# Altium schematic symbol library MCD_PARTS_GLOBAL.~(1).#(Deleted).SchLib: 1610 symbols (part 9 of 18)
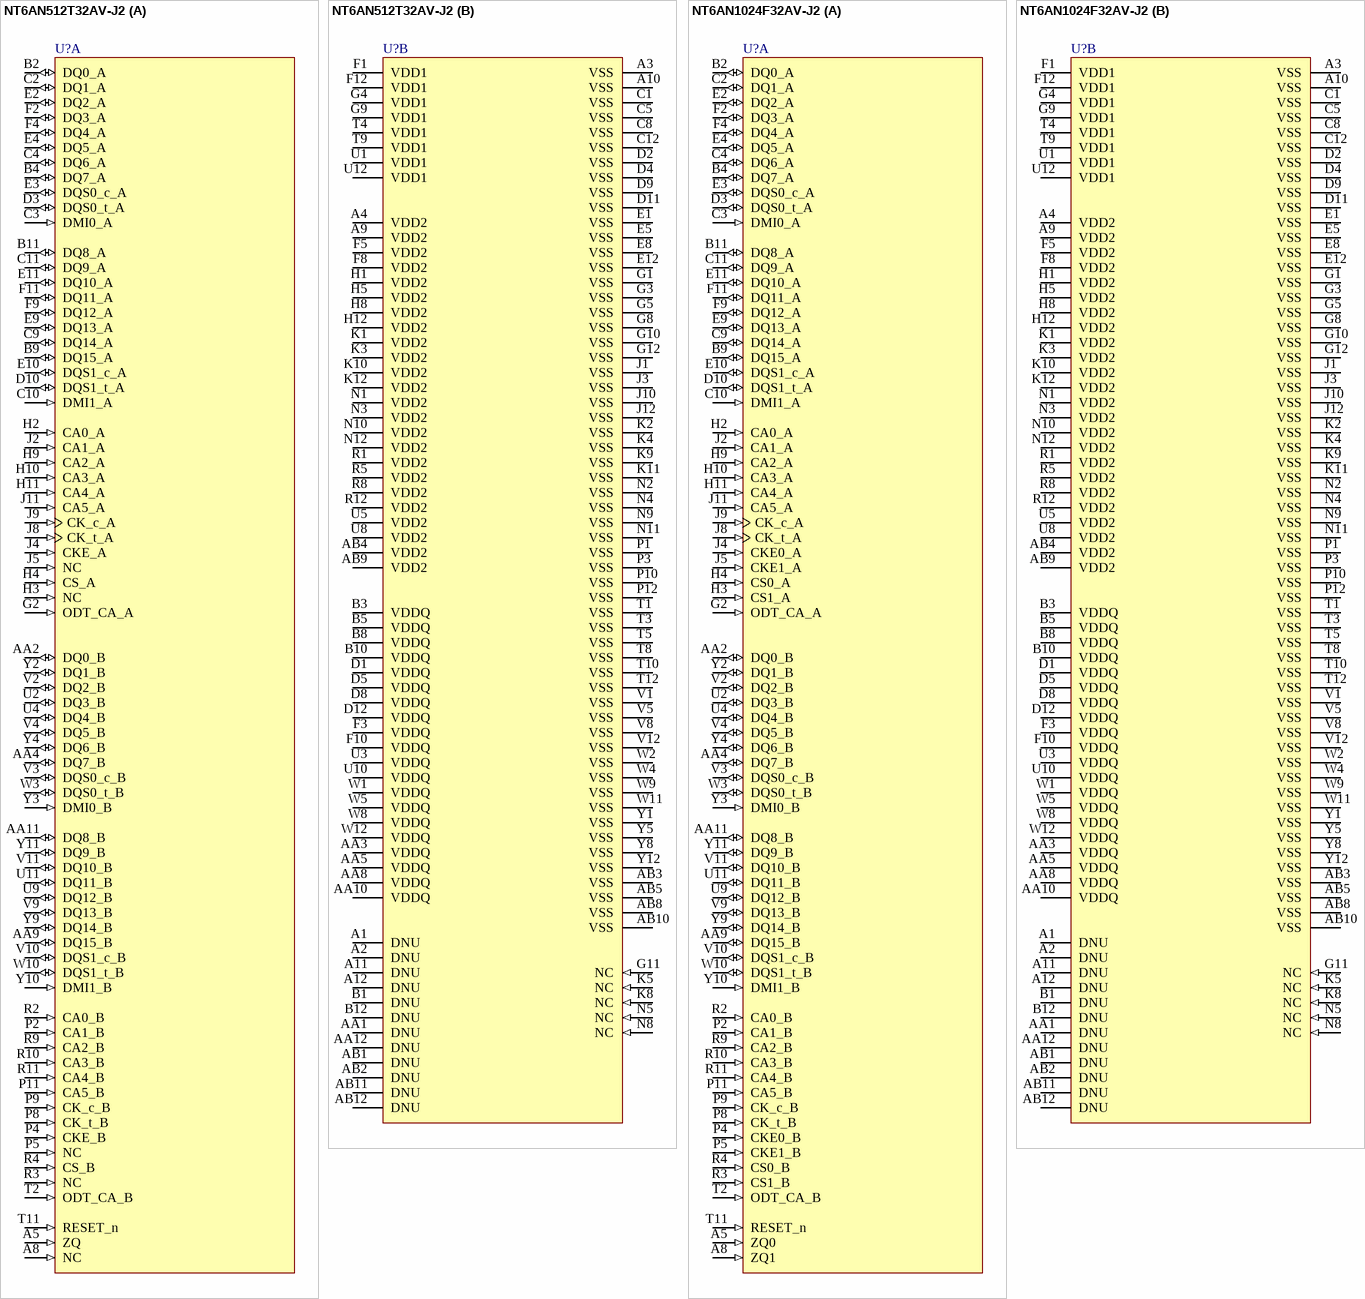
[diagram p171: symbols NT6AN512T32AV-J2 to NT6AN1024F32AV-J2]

## NT6AN1024F32AV-J2
designator U?
part A pins: A5 ZQ0 (in) "External impedance (240 ohm): This signal is used to calibrate the device output impedance.", A8 ZQ1 (in) "NC", AA2 DQ0_B (io) "Data input/output: Bidirectional data bus.", AA4 DQ7_B (io) "Data input/output: Bidirectional data bus.", AA9 DQ15_B (io) "Data input/output: Bidirectional data bus.", AA11 DQ8_B (io) "Data input/output: Bidirectional data bus.", B2 DQ0_A (io) "Data input/output: Bidirectional data bus.", B4 DQ7_A (io) "Data input/output: Bidirectional data bus.", B9 DQ15_A (io) "Data input/output: Bidirectional data bus.", B11 DQ8_A (io) "Data input/output: Bidirectional data bus.", C2 DQ1_A (io) "Data input/output: Bidirectional data bus.", C3 DMI0_A (in) "Input data mask: DM is an input mask signal for write data. Although DM ballsare input-only, the DM loading is designed to match that of DQ and DQS balls.DM[3:0] is DM for each of the four data bytes, respectively.", C4 DQ6_A (io) "Data input/output: Bidirectional data bus.", C9 DQ14_A (io) "Data input/output: Bidirectional data bus.", C10 DMI1_A (in) "Input data mask: DM is an input mask signal for write data. Although DM ballsare input-only, the DM loading is designed to match that of DQ and DQS balls.DM[3:0] is DM for each of the four data bytes, respectively.", C11 DQ9_A (io) "Data input/output: Bidirectional data bus.", D3 DQS0_t_A (io) "Data strobe: The data strobe is bidirectional (used for read and write data) andcomplementary (DQS and DQS#). It is edge-aligned output with read data andcentered input with write data. DQS[3:0]/DQS[3:0]# is DQS for each of (See Datasheet)", D10 DQS1_t_A (io) "Data strobe: The data strobe is bidirectional (used for read and write data) andcomplementary (DQS and DQS#). It is edge-aligned output with read data andcentered input with write data. DQS[3:0]/DQS[3:0]# is DQS for each of (See Datasheet)", E2 DQ2_A (io) "Data input/output: Bidirectional data bus.", E3 DQS0_c_A (io) "Data strobe: The data strobe is bidirectional (used for read and write data) andcomplementary (DQS and DQS#). It is edge-aligned output with read data andcentered input with write data. DQS[3:0]/DQS[3:0]# is DQS for each of (See Datasheet)", E4 DQ5_A (io) "Data input/output: Bidirectional data bus.", E9 DQ13_A (io) "Data input/output: Bidirectional data bus.", E10 DQS1_c_A (io) "Data strobe: The data strobe is bidirectional (used for read and write data) andcomplementary (DQS and DQS#). It is edge-aligned output with read data andcentered input with write data. DQS[3:0]/DQS[3:0]# is DQS for each of (See Datasheet)", E11 DQ10_A (io) "Data input/output: Bidirectional data bus.", F2 DQ3_A (io) "Data input/output: Bidirectional data bus.", F4 DQ4_A (io) "Data input/output: Bidirectional data bus.", F9 DQ12_A (io) "Data input/output: Bidirectional data bus.", F11 DQ11_A (io) "Data input/output: Bidirectional data bus.", G2 ODT_CA_A (in) "on die termination on CA", H2 CA0_A (in) "Command/address inputs: Provide the command and address inputs accordingto the command truth table.", H3 CS1_A (in) "NC", H4 CS0_A (in) "Chip select: CS# is considered part of the command code and is sampled at therising edge of CK.", H9 CA2_A (in) "Command/address inputs: Provide the command and address inputs accordingto the command truth table.", H10 CA3_A (in) "Command/address inputs: Provide the command and address inputs accordingto the command truth table.", H11 CA4_A (in) "Command/address inputs: Provide the command and address inputs accordingto the command truth table.", J2 CA1_A (in) "Command/address inputs: Provide the command and address inputs accordingto the command truth table.", J4 CKE0_A (in) "Clock enable: CKE HIGH activates and CKE LOW deactivates the internal clocksignals, input buffers, and output drivers. Power-saving modes are entered andexited via CKE transitions. CKE is considered part of the command code. (See Datasheet)", J5 CKE1_A (in) "NC", J8 CK_t_A (in) "Clock: CK and CK# are differential clock inputs. All CA inputs are sampled onboth rising and falling edges of CK. CS and CKE inputs are sampled at the risingedge of CK. AC timings are referenced to clock.", J9 CK_c_A (in) "Clock: CK and CK# are differential clock inputs. All CA inputs are sampled onboth rising and falling edges of CK. CS and CKE inputs are sampled at the risingedge of CK. AC timings are referenced to clock.", J11 CA5_A (in) "Command/address inputs: Provide the command and address inputs accordingto the command truth table.", P2 CA1_B (in) "Command/address inputs: Provide the command and address inputs accordingto the command truth table.", P4 CKE0_B (in) "Clock enable: CKE HIGH activates and CKE LOW deactivates the internal clocksignals, input buffers, and output drivers. Power-saving modes are entered andexited via CKE transitions. CKE is considered part of the command code. (See Datasheet)", P5 CKE1_B (in) "NC", P8 CK_t_B (in) "Clock: CK and CK# are differential clock inputs. All CA inputs are sampled onboth rising and falling edges of CK. CS and CKE inputs are sampled at the risingedge of CK. AC timings are referenced to clock.", P9 CK_c_B (in) "Clock: CK and CK# are differential clock inputs. All CA inputs are sampled onboth rising and falling edges of CK. CS and CKE inputs are sampled at the risingedge of CK. AC timings are referenced to clock.", P11 CA5_B (in) "Command/address inputs: Provide the command and address inputs accordingto the command truth table.", R2 CA0_B (in) "Command/address inputs: Provide the command and address inputs accordingto the command truth table.", R3 CS1_B (in) "NC", R4 CS0_B (in) "Chip select: CS# is considered part of the command code and is sampled at therising edge of CK.", R9 CA2_B (in) "Command/address inputs: Provide the command and address inputs accordingto the command truth table.", R10 CA3_B (in) "Command/address inputs: Provide the command and address inputs accordingto the command truth table.", R11 CA4_B (in) "Command/address inputs: Provide the command and address inputs accordingto the command truth table.", T2 ODT_CA_B (in) "on die termination on CA", T11 RESET_n (in) "Reset active low", U2 DQ3_B (io) "Data input/output: Bidirectional data bus.", U4 DQ4_B (io) "Data input/output: Bidirectional data bus.", U9 DQ12_B (io) "Data input/output: Bidirectional data bus.", U11 DQ11_B (io) "Data input/output: Bidirectional data bus.", V2 DQ2_B (io) "Data input/output: Bidirectional data bus.", V3 DQS0_c_B (io) "Data strobe: The data strobe is bidirectional (used for read and write data) andcomplementary (DQS and DQS#). It is edge-aligned output with read data andcentered input with write data. DQS[3:0]/DQS[3:0]# is DQS for each of (See Datasheet)", V4 DQ5_B (io) "Data input/output: Bidirectional data bus.", V9 DQ13_B (io) "Data input/output: Bidirectional data bus.", V10 DQS1_c_B (io) "Data strobe: The data strobe is bidirectional (used for read and write data) andcomplementary (DQS and DQS#). It is edge-aligned output with read data andcentered input with write data. DQS[3:0]/DQS[3:0]# is DQS for each of (See Datasheet)", V11 DQ10_B (io) "Data input/output: Bidirectional data bus.", W3 DQS0_t_B (io) "Data strobe: The data strobe is bidirectional (used for read and write data) andcomplementary (DQS and DQS#). It is edge-aligned output with read data andcentered input with write data. DQS[3:0]/DQS[3:0]# is DQS for each of (See Datasheet)", W10 DQS1_t_B (io) "Data strobe: The data strobe is bidirectional (used for read and write data) andcomplementary (DQS and DQS#). It is edge-aligned output with read data andcentered input with write data. DQS[3:0]/DQS[3:0]# is DQS for each of (See Datasheet)", Y2 DQ1_B (io) "Data input/output: Bidirectional data bus.", Y3 DMI0_B (in) "Input data mask: DM is an input mask signal for write data. Although DM ballsare input-only, the DM loading is designed to match that of DQ and DQS balls.DM[3:0] is DM for each of the four data bytes, respectively.", Y4 DQ6_B (io) "Data input/output: Bidirectional data bus.", Y9 DQ14_B (io) "Data input/output: Bidirectional data bus.", Y10 DMI1_B (in) "Input data mask: DM is an input mask signal for write data. Although DM ballsare input-only, the DM loading is designed to match that of DQ and DQS balls.DM[3:0] is DM for each of the four data bytes, respectively.", Y11 DQ9_B (io) "Data input/output: Bidirectional data bus."
part B pins: A1 DNU "Do not use: Must be grounded or left floating.", A2 DNU "Do not use: Must be grounded or left floating.", A3 VSS (power) "Common ground.", A4 VDD2 (power) "Core power: Supply 2.", A9 VDD2 (power) "Core power: Supply 2.", A10 VSS (power) "Common ground.", A11 DNU "Do not use: Must be grounded or left floating.", A12 DNU "Do not use: Must be grounded or left floating.", AA1 DNU "Do not use: Must be grounded or left floating.", AA3 VDDQ (power) "DQ power supply: Isolated on the die for improved noise immunity.", AA5 VDDQ (power) "DQ power supply: Isolated on the die for improved noise immunity.", AA8 VDDQ (power) "DQ power supply: Isolated on the die for improved noise immunity.", AA10 VDDQ (power) "DQ power supply: Isolated on the die for improved noise immunity.", AA12 DNU "Do not use: Must be grounded or left floating.", AB1 DNU "Do not use: Must be grounded or left floating.", AB2 DNU "Do not use: Must be grounded or left floating.", AB3 VSS "Common ground.", AB4 VDD2 (power) "Core power: Supply 2.", AB5 VSS "Common ground.", AB8 VSS "Common ground.", AB9 VDD2 (power) "Core power: Supply 2.", AB10 VSS "Common ground.", AB11 DNU "Do not use: Must be grounded or left floating.", AB12 DNU "Do not use: Must be grounded or left floating.", B1 DNU "Do not use: Must be grounded or left floating.", B3 VDDQ (power) "DQ power supply: Isolated on the die for improved noise immunity.", B5 VDDQ (power) "DQ power supply: Isolated on the die for improved noise immunity.", B8 VDDQ (power) "DQ power supply: Isolated on the die for improved noise immunity.", B10 VDDQ (power) "DQ power supply: Isolated on the die for improved noise immunity.", B12 DNU "Do not use: Must be grounded or left floating.", C1 VSS (power) "Common ground.", C5 VSS (power) "Common ground.", C8 VSS (power) "Common ground.", C12 VSS (power) "Common ground.", D1 VDDQ (power) "DQ power supply: Isolated on the die for improved noise immunity.", D2 VSS (power) "Common ground.", D4 VSS (power) "Common ground.", D5 VDDQ (power) "DQ power supply: Isolated on the die for improved noise immunity.", D8 VDDQ (power) "DQ power supply: Isolated on the die for improved noise immunity.", D9 VSS (power) "Common ground.", D11 VSS (power) "Common ground.", D12 VDDQ (power) "DQ power supply: Isolated on the die for improved noise immunity.", E1 VSS (power) "Common ground.", E5 VSS (power) "Common ground.", E8 VSS (power) "Common ground.", E12 VSS (power) "Common ground.", F1 VDD1 (power) "Core power: Supply 1.", F3 VDDQ (power) "DQ power supply: Isolated on the die for improved noise immunity.", F5 VDD2 (power) "Core power: Supply 2.", F8 VDD2 (power) "Core power: Supply 2.", F10 VDDQ (power) "DQ power supply: Isolated on the die for improved noise immunity.", F12 VDD1 (power) "Core power: Supply 1.", G1 VSS (power) "Common ground.", G3 VSS (power) "Common ground.", G4 VDD1 (power) "Core power: Supply 1.", G5 VSS (power) "Common ground.", G8 VSS (power) "Common ground.", G9 VDD1 (power) "Core power: Supply 1.", G10 VSS (power) "Common ground.", G11 NC (in) "Not connected", G12 VSS (power) "Common ground.", H1 VDD2 (power) "Core power: Supply 2.", H5 VDD2 (power) "Core power: Supply 2.", H8 VDD2 (power) "Core power: Supply 2.", H12 VDD2 (power) "Core power: Supply 2.", J1 VSS (power) "Common ground.", J3 VSS (power) "Common ground.", J10 VSS (power) "Common ground.", J12 VSS (power) "Common ground.", K1 VDD2 (power) "Core power: Supply 2.", K2 VSS (power) "Common ground.", K3 VDD2 (power) "Core power: Supply 2.", K4 VSS (power) "Common ground.", K5 NC (in) "Not connected", K8 NC (in) "Not connected", K9 VSS (power) "Common ground.", K10 VDD2 (power) "Core power: Supply 2.", K11 VSS "Common ground.", K12 VDD2 (power) "Core power: Supply 2.", N1 VDD2 (power) "Core power: Supply 2.", N2 VSS "Common ground.", N3 VDD2 (power) "Core power: Supply 2.", N4 VSS "Common ground.", N5 NC (in) "Not connected", N8 NC (in) "Not connected", N9 VSS "Common ground.", N10 VDD2 (power) "Core power: Supply 2.", N11 VSS "Common ground.", N12 VDD2 (power) "Core power: Supply 2.", P1 VSS "Common ground.", P3 VSS (power) "Common ground.", P10 VSS (power) "Common ground.", P12 VSS "Common ground.", R1 VDD2 (power) "Core power: Supply 2.", R5 VDD2 (power) "Core power: Supply 2.", R8 VDD2 (power) "Core power: Supply 2.", R12 VDD2 (power) "Core power: Supply 2.", T1 VSS "Common ground.", T3 VSS "Common ground.", T4 VDD1 (power) "Core power: Supply 1.", T5 VSS "Common ground.", T8 VSS "Common ground.", T9 VDD1 (power) "Core power: Supply 1.", T10 VSS "Common ground.", T12 VSS "Common ground.", U1 VDD1 (power) "Core power: Supply 1.", U3 VDDQ (power) "DQ power supply: Isolated on the die for improved noise immunity.", U5 VDD2 (power) "Core power: Supply 2.", U8 VDD2 (power) "Core power: Supply 2.", U10 VDDQ (power) "DQ power supply: Isolated on the die for improved noise immunity.", U12 VDD1 (power) "Core power: Supply 1.", V1 VSS (power) "Common ground.", V5 VSS (power) "Common ground.", V8 VSS "Common ground.", V12 VSS "Common ground.", W1 VDDQ (power) "DQ power supply: Isolated on the die for improved noise immunity.", W2 VSS "Common ground.", W4 VSS "Common ground.", W5 VDDQ (power) "DQ power supply: Isolated on the die for improved noise immunity.", W8 VDDQ (power) "DQ power supply: Isolated on the die for improved noise immunity.", W9 VSS "Common ground.", W11 VSS "Common ground.", W12 VDDQ (power) "DQ power supply: Isolated on the die for improved noise immunity.", Y1 VSS "Common ground.", Y5 VSS "Common ground.", Y8 VSS "Common ground.", Y12 VSS "Common ground."

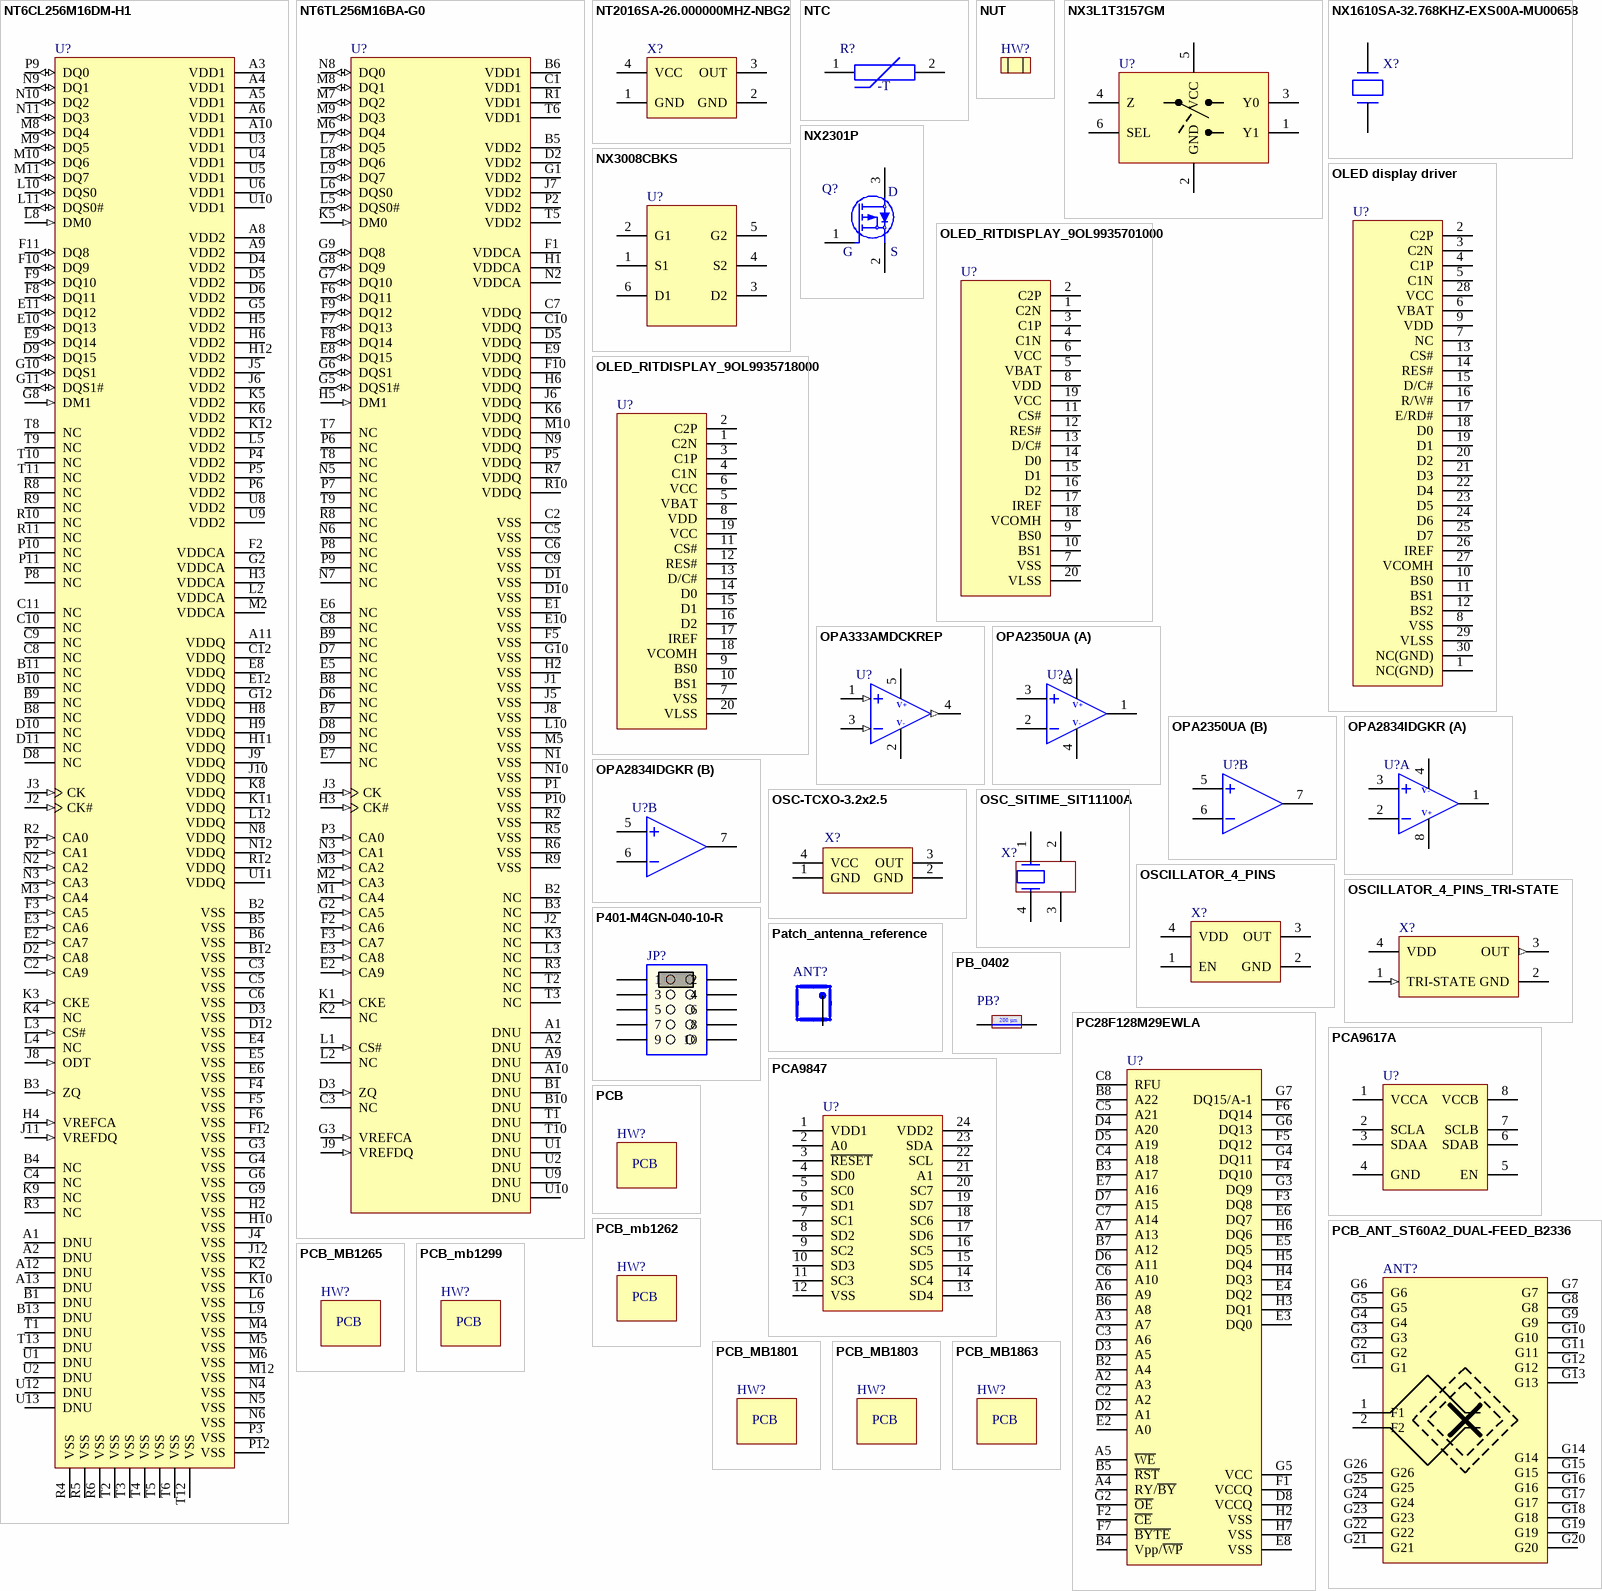
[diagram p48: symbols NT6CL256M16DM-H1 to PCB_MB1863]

## NT6CL256M16DM-H1
designator U?
pins: A1 DNU "Do not use: Must be grounded or left floating.", A2 DNU "Do not use: Must be grounded or left floating.", A3 VDD1 (power) "Core power: Supply 1.", A4 VDD1 (power) "Core power: Supply 1.", A5 VDD1 (power) "Core power: Supply 1.", A6 VDD1 (power) "Core power: Supply 1.", A8 VDD2 (power) "Core power: Supply 2.", A9 VDD2 (power) "Core power: Supply 2.", A10 VDD1 (power) "Core power: Supply 1.", A11 VDDQ (power) "DQ power supply: Isolated on the die for improved noise immunity.", A12 DNU "Do not use: Must be grounded or left floating.", A13 DNU "Do not use: Must be grounded or left floating.", B1 DNU "Do not use: Must be grounded or left floating.", B2 VSS (power) "Common ground", B3 ZQ (in) "External impedance (240 ohm): This signal is used to calibrate the device output impedance.", B4 NC "No connect: Not internally connected.", B5 VSS (power) "Common ground", B6 VSS (power) "Common ground", B8 NC "No connect: Not internally connected.", B9 NC "No connect: Not internally connected.", B10 NC "No connect: Not internally connected.", B11 NC "No connect: Not internally connected.", B12 VSS (power) "Common ground", B13 DNU "Do not use: Must be grounded or left floating.", C2 CA9 (in) "Command/address inputs: Provide the command and address inputs accordingto the command truth table.", C3 VSS (power) "Common ground", C4 NC "No connect: Not internally connected.", C5 VSS (power) "Common ground", C6 VSS (power) "Common ground", C8 NC "No connect: Not internally connected.", C9 NC "No connect: Not internally connected.", C10 NC "No connect: Not internally connected.", C11 NC "No connect: Not internally connected.", C12 VDDQ (power) "DQ power supply: Isolated on the die for improved noise immunity.", D2 CA8 (in) "Command/address inputs: Provide the command and address inputs accordingto the command truth table.", D3 VSS (power) "Common ground", D4 VDD2 (power) "Core power: Supply 2.", D5 VDD2 (power) "Core power: Supply 2.", D6 VDD2 (power) "Core power: Supply 2.", D8 NC "No connect: Not internally connected.", D9 DQ15 (io) "Data input/output: Bidirectional data bus.", D10 NC "No connect: Not internally connected.", D11 NC "No connect: Not internally connected.", D12 VSS (power) "Common ground", E2 CA7 (in) "Command/address inputs: Provide the command and address inputs accordingto the command truth table.", E3 CA6 (in) "Command/address inputs: Provide the command and address inputs accordingto the command truth table.", E4 VSS (power) "Common ground", E5 VSS (power) "Common ground", E6 VSS (power) "Common ground", E8 VDDQ (power) "DQ power supply: Isolated on the die for improved noise immunity.", E9 DQ14 (io) "Data input/output: Bidirectional data bus.", E10 DQ13 (io) "Data input/output: Bidirectional data bus.", E11 DQ12 (io) "Data input/output: Bidirectional data bus.", E12 VDDQ (power) "DQ power supply: Isolated on the die for improved noise immunity.", F2 VDDCA (power) "Command/address power supply: Command/address power supply.", F3 CA5 (in) "Command/address inputs: Provide the command and address inputs accordingto the command truth table.", F4 VSS (power) "Common ground", F5 VSS (power) "Common ground", F6 VSS (power) "Common ground", F8 DQ11 (io) "Data input/output: Bidirectional data bus.", F9 DQ10 (io) "Data input/output: Bidirectional data bus.", F10 DQ9 (io) "Data input/output: Bidirectional data bus.", F11 DQ8 (io) "Data input/output: Bidirectional data bus.", F12 VSS (power) "Common ground", G2 VDDCA (power) "Command/address power supply: Command/address power supply.", G3 VSS (power) "Common ground", G4 VSS (power) "Common ground", G5 VDD2 (power) "Core power: Supply 2.", G6 VSS (power) "Common ground", G8 DM1 (in) "Input data mask: DM is an input mask signal for write data. Although DM ballsare input-only, the DM loading is designed to match that of DQ and DQS balls.DM[3:0] is DM for each of the four data bytes, respectively.", G9 VSS (power) "Common ground", G10 DQS1 (io) "Data strobe: The data strobe is bidirectional (used for read and write data) andcomplementary (DQS and DQS#). It is edge-aligned output with read data andcentered input with write data. DQS[3:0]/DQS[3:0]# is DQS for each of (See Datasheet)", G11 DQS1# (io) "Data strobe: The data strobe is bidirectional (used for read and write data) andcomplementary (DQS and DQS#). It is edge-aligned output with read data andcentered input with write data. DQS[3:0]/DQS[3:0]# is DQS for each of (See Datasheet)", G12 VDDQ (power) "DQ power supply: Isolated on the die for improved noise immunity.", H2 VSS (power) "Common ground", H3 VDDCA (power) "Command/address power supply: Command/address power supply.", H4 VREFCA (in) "Reference voltage: VREFCA is reference for command/address input buffers,VREFDQ is reference for DQ input buffers.", H5 VDD2 (power) "Core power: Supply 2.", H6 VDD2 (power) "Core power: Supply 2.", H8 VDDQ (power) "DQ power supply: Isolated on the die for improved noise immunity.", H9 VDDQ (power) "DQ power supply: Isolated on the die for improved noise immunity.", H10 VSS (power) "Common ground", H11 VDDQ (power) "DQ power supply: Isolated on the die for improved noise immunity.", H12 VDD2 (power) "Core power: Supply 2.", J2 CK# (in) "Clock: CK and CK# are differential clock inputs. All CA inputs are sampled onboth rising and falling edges of CK. CS and CKE inputs are sampled at the risingedge of CK. AC timings are referenced to clock.", J3 CK (in) "Clock: CK and CK# are differential clock inputs. All CA inputs are sampled onboth rising and falling edges of CK. CS and CKE inputs are sampled at the risingedge of CK. AC timings are referenced to clock.", J4 VSS (power) "Common ground", J5 VDD2 (power) "Core power: Supply 2.", J6 VDD2 (power) "Core power: Supply 2.", J8 ODT (in) "On Die Termination. If ODT function is not used, pin is NC.", J9 VDDQ (power) "DQ power supply: Isolated on the die for improved noise immunity.", J10 VDDQ (power) "DQ power supply: Isolated on the die for improved noise immunity.", J11 VREFDQ (in) "Reference voltage: VREFCA is reference for command/address input buffers,VREFDQ is reference for DQ input buffers.", J12 VSS (power) "Common ground", K2 VSS (power) "Common ground", K3 CKE (in) "Clock enable: CKE HIGH activates and CKE LOW deactivates the internal clocksignals, input buffers, and output drivers. Power-saving modes are entered andexited via CKE transitions. CKE is considered part of the command code. (See Datasheet)", K4 NC "No connect: Not internally connected.", K5 VDD2 (power) "Core power: Supply 2.", K6 VDD2 (power) "Core power: Supply 2.", K8 VDDQ (power) "DQ power supply: Isolated on the die for improved noise immunity.", K9 NC "No connect: Not internally connected.", K10 VSS (power) "Common ground", K11 VDDQ (power) "DQ power supply: Isolated on the die for improved noise immunity.", K12 VDD2 (power) "Core power: Supply 2.", L2 VDDCA (power) "Command/address power supply: Command/address power supply.", L3 CS# (in) "Chip select: CS# is considered part of the command code and is sampled at therising edge of CK.", L4 NC "No connect: Not internally connected.", L5 VDD2 (power) "Core power: Supply 2.", L6 VSS (power) "Common ground", L8 DM0 (in) "Input data mask: DM is an input mask signal for write data. Although DM ballsare input-only, the DM loading is designed to match that of DQ and DQS balls.DM[3:0] is DM for each of the four data bytes, respectively.", L9 VSS (power) "Common ground", L10 DQS0 (io) "Data strobe: The data strobe is bidirectional (used for read and write data) andcomplementary (DQS and DQS#). It is edge-aligned output with read data andcentered input with write data. DQS[3:0]/DQS[3:0]# is DQS for each of (See Datasheet)", L11 DQS0# (io) "Data strobe: The data strobe is bidirectional (used for read and write data) andcomplementary (DQS and DQS#). It is edge-aligned output with read data andcentered input with write data. DQS[3:0]/DQS[3:0]# is DQS for each of (See Datasheet)", L12 VDDQ (power) "DQ power supply: Isolated on the die for improved noise immunity.", M2 VDDCA (power) "Command/address power supply: Command/address power supply.", M3 CA4 (in) "Command/address inputs: Provide the command and address inputs accordingto the command truth table.", M4 VSS (power) "Common ground", M5 VSS (power) "Common ground", M6 VSS (power) "Common ground", M8 DQ4 (io) "Data input/output: Bidirectional data bus.", M9 DQ5 (io) "Data input/output: Bidirectional data bus.", M10 DQ6 (io) "Data input/output: Bidirectional data bus.", M11 DQ7 (io) "Data input/output: Bidirectional data bus.", M12 VSS (power) "Common ground", N2 CA2 (in) "Command/address inputs: Provide the command and address inputs accordingto the command truth table.", N3 CA3 (in) "Command/address inputs: Provide the command and address inputs accordingto the command truth table.", N4 VSS (power) "Common ground", N5 VSS (power) "Common ground", N6 VSS (power) "Common ground", N8 VDDQ (power) "DQ power supply: Isolated on the die for improved noise immunity.", N9 DQ1 (io) "Data input/output: Bidirectional data bus.", N10 DQ2 (io) "Data input/output: Bidirectional data bus.", N11 DQ3 (io) "Data input/output: Bidirectional data bus.", N12 VDDQ (power) "DQ power supply: Isolated on the die for improved noise immunity.", P2 CA1 (in) "Command/address inputs: Provide the command and address inputs accordingto the command truth table.", P3 VSS (power) "Common ground", P4 VDD2 (power) "Core power: Supply 2.", P5 VDD2 (power) "Core power: Supply 2.", P6 VDD2 (power) "Core power: Supply 2.", P8 NC "No connect: Not internally connected.", P9 DQ0 (io) "Data input/output: Bidirectional data bus.", P10 NC "No connect: Not internally connected.", P11 NC "No connect: Not internally connected.", P12 VSS (power) "Common ground", R2 CA0 (in) "Command/address inputs: Provide the command and address inputs accordingto the command truth table.", R3 NC "No connect: Not internally connected.", R4 VSS (power) "Common ground", R5 VSS (power) "Common ground", R6 VSS (power) "Common ground", R8 NC "No connect: Not internally connected.", R9 NC "No connect: Not internally connected.", R10 NC "No connect: Not internally connected.", R11 NC "No connect: Not internally connected.", R12 VDDQ (power) "DQ power supply: Isolated on the die for improved noise immunity.", T1 DNU "Do not use: Must be grounded or left floating.", T2 VSS (power) "Common ground", T3 VSS (power) "Common ground", T4 VSS (power) "Common ground", T5 VSS (power) "Common ground", T6 VSS (power) "Common ground", T8 NC "No connect: Not internally connected.", T9 NC "No connect: Not internally connected.", T10 NC "No connect: Not internally connected.", T11 NC "No connect: Not internally connected.", T12 VSS (power) "Common ground", T13 DNU "Do not use: Must be grounded or left floating.", U1 DNU "Do not use: Must be grounded or left floating.", U2 DNU "Do not use: Must be grounded or left floating.", U3 VDD1 (power) "Core power: Supply 1.", U4 VDD1 (power) "Core power: Supply 1.", U5 VDD1 (power) "Core power: Supply 1.", U6 VDD1 (power) "Core power: Supply 1.", U8 VDD2 (power) "Core power: Supply 2.", U9 VDD2 (power) "Core power: Supply 2.", U10 VDD1 (power) "Core power: Supply 1.", U11 VDDQ (power) "DQ power supply: Isolated on the die for improved noise immunity.", U12 DNU "Do not use: Must be grounded or left floating.", U13 DNU "Do not use: Must be grounded or left floating."

## NT6TL256M16BA-G0
designator U?
pins: A1 DNU "Do not use: Must be grounded or left floating.", A2 DNU "Do not use: Must be grounded or left floating.", A9 DNU "Do not use: Must be grounded or left floating.", A10 DNU "Do not use: Must be grounded or left floating.", B1 DNU "Do not use: Must be grounded or left floating.", B2 NC "No connect: Not internally connected.", B3 NC "No connect: Not internally connected.", B5 VDD2 (power) "Core power: Supply 2.", B6 VDD1 (power) "Core power: Supply 1.", B7 NC "No connect: Not internally connected.", B8 NC "No connect: Not internally connected.", B9 NC "No connect: Not internally connected.", B10 DNU "Do not use: Must be grounded or left floating.", C1 VDD1 (power) "Core power: Supply 1.", C2 VSS (power) "Common ground.", C3 NC "No connect: Not internally connected.", C5 VSS (power) "Common ground.", C6 VSS (power) "Common ground.", C7 VDDQ (power) "DQ power supply: Isolated on the die for improved noise immunity.", C8 NC "No connect: Not internally connected.", C9 VSS (power) "Common ground.", C10 VDDQ (power) "DQ power supply: Isolated on the die for improved noise immunity.", D1 VSS (power) "Common ground", D2 VDD2 (power) "Core power: Supply 2.", D3 ZQ (in) "External impedance (240 ohm): This signal is used to calibrate the device output impedance.", D5 VDDQ (power) "DQ power supply: Isolated on the die for improved noise immunity.", D6 NC "No connect: Not internally connected.", D7 NC "No connect: Not internally connected.", D8 NC "No connect: Not internally connected.", D9 NC "No connect: Not internally connected.", D10 VSS (power) "Common ground.", E1 VSS (power) "Common ground.", E2 CA9 (in) "Command/address inputs: Provide the command and address inputs accordingto the command truth table.", E3 CA8 (in) "Command/address inputs: Provide the command and address inputs accordingto the command truth table.", E5 NC "No connect: Not internally connected.", E6 NC "No connect: Not internally connected.", E7 NC "No connect: Not internally connected.", E8 DQ15 (io) "Data input/output: Bidirectional data bus.", E9 VDDQ (power) "DQ power supply: Isolated on the die for improved noise immunity.", E10 VSS (power) "Common ground.", F1 VDDCA (power) "Command/address power supply: Command/address power supply.", F2 CA6 (in) "Command/address inputs: Provide the command and address inputs accordingto the command truth table.", F3 CA7 (in) "Command/address inputs: Provide the command and address inputs accordingto the command truth table.", F5 VSS (power) "Common ground.", F6 DQ11 (io) "Data input/output: Bidirectional data bus.", F7 DQ13 (io) "Data input/output: Bidirectional data bus.", F8 DQ14 (io) "Data input/output: Bidirectional data bus.", F9 DQ12 (io) "Data input/output: Bidirectional data bus.", F10 VDDQ (power) "DQ power supply: Isolated on the die for improved noise immunity.", G1 VDD2 (power) "Core power: Supply 2.", G2 CA5 (in) "Command/address inputs: Provide the command and address inputs accordingto the command truth table.", G3 VREFCA (in) "Reference voltage: VREFCA is reference for command/address input buffers,VREFDQ is reference for DQ input buffers.", G5 DQS1# (io) "Data strobe: The data strobe is bidirectional (used for read and write data) andcomplementary (DQS and DQS#). It is edge-aligned output with read data andcentered input with write data. DQS[1:0]/DQS[1:0]# is DQS for each of (See Datasheet)", G6 DQS1 (io) "Data strobe: The data strobe is bidirectional (used for read and write data) andcomplementary (DQS and DQS#). It is edge-aligned output with read data andcentered input with write data. DQS[1:0]/DQS[1:0]# is DQS for each of (See Datasheet)", G7 DQ10 (io) "Data input/output: Bidirectional data bus.", G8 DQ9 (io) "Data input/output: Bidirectional data bus.", G9 DQ8 (io) "Data input/output: Bidirectional data bus.", G10 VSS (power) "Common ground.", H1 VDDCA (power) "Command/address power supply: Command/address power supply.", H2 VSS (power) "Common ground", H3 CK# (in) "Clock: CK and CK# are differential clock inputs. All CA inputs are sampled onboth rising and falling edges of CK. CS and CKE inputs are sampled at the risingedge of CK. AC timings are referenced to clock.", H5 DM1 (in) "Input data mask: DM is an input mask signal for write data. Although DM ballsare input-only, the DM loading is designed to match that of DQ and DQS balls.DM[3:0] is DM for each of the four data bytes, respectively.", H6 VDDQ (power) "DQ power supply: Isolated on the die for improved noise immunity.", J1 VSS (power) "Common ground.", J2 NC "No connect: Not internally connected.", J3 CK (in) "Clock: CK and CK# are differential clock inputs. All CA inputs are sampled onboth rising and falling edges of CK. CS and CKE inputs are sampled at the risingedge of CK. AC timings are referenced to clock.", J5 VSS (power) "Common ground.", J6 VDDQ (power) "DQ power supply: Isolated on the die for improved noise immunity.", J7 VDD2 (power) "Core power: Supply 2.", J8 VSS (power) "Common ground", J9 VREFDQ (in) "Reference voltage: VREFCA is reference for command/address input buffers,VREFDQ is reference for DQ input buffers.", K1 CKE (in) "Clock enable: CKE HIGH activates and CKE LOW deactivates the internal clocksignals, input buffers, and output drivers. Power-saving modes are entered andexited via CKE transitions. CKE is considered part of the command code. (See Datasheet)", K2 NC "No connect: Not internally connected.", K3 NC "No connect: Not internally connected.", K5 DM0 (in) "Input data mask: DM is an input mask signal for write data. Although DM ballsare input-only, the DM loading is designed to match that of DQ and DQS balls.DM[3:0] is DM for each of the four data bytes, respectively.", K6 VDDQ (power) "DQ power supply: Isolated on the die for improved noise immunity.", L1 CS# (in) "Chip select: CS# is considered part of the command code and is sampled at therising edge of CK.", L2 NC "No connect: Not internally connected.", L3 NC "No connect: Not internally connected.", L5 DQS0# (io) "Data strobe: The data strobe is bidirectional (used for read and write data) andcomplementary (DQS and DQS#). It is edge-aligned output with read data andcentered input with write data. DQS[1:0]/DQS[1:0]# is DQS for each of (See Datasheet)", L6 DQS0 (io) "Data strobe: The data strobe is bidirectional (used for read and write data) andcomplementary (DQS and DQS#). It is edge-aligned output with read data andcentered input with write data. DQS[1:0]/DQS[1:0]# is DQS for each of (See Datasheet)", L7 DQ5 (io) "Data input/output: Bidirectional data bus.", L8 DQ6 (io) "Data input/output: Bidirectional data bus.", L9 DQ7 (io) "Data input/output: Bidirectional data bus.", L10 VSS (power) "Common ground.", M1 CA4 (in) "Command/address inputs: Provide the command and address inputs accordingto the command truth table.", M2 CA3 (in) "Command/address inputs: Provide the command and address inputs accordingto the command truth table.", M3 CA2 (in) "Command/address inputs: Provide the command and address inputs accordingto the command truth table.", M5 VSS (power) "Common ground.", M6 DQ4 (io) "Data input/output: Bidirectional data bus.", M7 DQ2 (io) "Data input/output: Bidirectional data bus.", M8 DQ1 (io) "Data input/output: Bidirectional data bus.", M9 DQ3 (io) "Data input/output: Bidirectional data bus.", M10 VDDQ (power) "DQ power supply: Isolated on the die for improved noise immunity.", N1 VSS (power) "Common ground.", N2 VDDCA (power) "Command/address power supply: Command/address power supply.", N3 CA1 (in) "Command/address inputs: Provide the command and address inputs accordingto the command truth table.", N5 NC "No connect: Not internally connected.", N6 NC "No connect: Not internally connected.", N7 NC "No connect: Not internally connected.", N8 DQ0 (io) "Data input/output: Bidirectional data bus.", N9 VDDQ (power) "DQ power supply: Isolated on the die for improved noise immunity.", N10 VSS (power) "Common ground.", P1 VSS (power) "Common ground", P2 VDD2 (power) "Core power: Supply 2.", P3 CA0 (in) "Command/address inputs: Provide the command and address inputs accordingto the command truth table.", P5 VDDQ (power) "DQ power supply: Isolated on the die for improved noise immunity.", P6 NC "No connect: Not internally connected.", P7 NC "No connect: Not internally connected.", P8 NC "No connect: Not internally connected.", P9 NC "No connect: Not internally connected.", P10 VSS (power) "Common ground.", R1 VDD1 (power) "Core power: Supply 1.", R2 VSS (power) "Common ground", R3 NC "No connect: Not internally connected.", R5 VSS (power) "Common ground", R6 VSS (power) "Common ground.", R7 VDDQ (power) "DQ power supply: Isolated on the die for improved noise immunity.", R8 NC "No connect: Not internally connected.", R9 VSS (power) "Common ground.", R10 VDDQ (power) "DQ power supply: Isolated on the die for improved noise immunity.", T1 DNU "Do not use: Must be grounded or left floating.", T2 NC "No connect: Not internally connected.", T3 NC "No connect: Not internally connected.", T5 VDD2 (power) "Core power: Supply 2.", T6 VDD1 (power) "Core power: Supply 1.", T7 NC "No connect: Not internally connected.", T8 NC "No connect: Not internally connected.", T9 NC "No connect: Not internally connected.", T10 DNU "Do not use: Must be grounded or left floating.", U1 DNU "Do not use: Must be grounded or left floating.", U2 DNU "Do not use: Must be grounded or left floating.", U9 DNU "Do not use: Must be grounded or left floating.", U10 DNU "Do not use: Must be grounded or left floating."

## NT2016SA-26.000000MHZ-NBG2
designator X?
pins: 1 GND, 2 GND, 3 OUT, 4 VCC

## NTC
designator R?
pins: 1, 2

## NUT
designator HW?  (mechanical)

## NX3L1T3157GM
designator U?
pins: 1 Y1, 2 GND, 3 Y0, 4 Z, 5 VCC, 6 SEL

## NX1610SA-32.768KHZ-EXS00A-MU00658
designator X?
pins: 1 X1, 2 X2

## NX2301P
designator Q?
pins: 1 G, 2 S, 3 D

## NX3008CBKS
designator U?
pins: 1 S1, 2 G1, 3 D2, 4 S2, 5 G2, 6 D1

## OLED display driver
designator U?
pins: 1 NC(GND), 2 C2P, 3 C2N, 4 C1P, 5 C1N, 6 VBAT, 7 NC, 8 VSS, 9 VDD, 10 BS0, 11 BS1, 12 BS2, 13 CS#, 14 RES#, 15 D/C#, 16 R/W#, 17 E/RD#, 18 D0, 19 D1, 20 D2, 21 D3, 22 D4, 23 D5, 24 D6, 25 D7, 26 IREF, 27 VCOMH, 28 VCC, 29 VLSS, 30 NC(GND)

## OLED_RITDISPLAY_9OL9935701000
designator U?
pins: 1 C2N, 2 C2P, 3 C1P, 4 C1N, 5 VBAT, 6 VCC, 7 VSS, 8 VDD, 9 BS0, 10 BS1, 11 CS#, 12 RES#, 13 D/C#, 14 D0, 15 D1, 16 D2, 17 IREF, 18 VCOMH, 19 VCC, 20 VLSS

## OLED_RITDISPLAY_9OL9935718000
designator U?
pins: 1 C2N, 2 C2P, 3 C1P, 4 C1N, 5 VBAT, 6 VCC, 7 VSS, 8 VDD, 9 BS0, 10 BS1, 11 CS#, 12 RES#, 13 D/C#, 14 D0, 15 D1, 16 D2, 17 IREF, 18 VCOMH, 19 VCC, 20 VLSS

## OPA333AMDCKREP
designator U?
pins: 1 (in), 2 (power), 3 (in), 4 (out), 5 (power)

## OPA2350UA
designator U?
part A pins: 1, 2, 3, 4, 8
part B pins: 5, 6, 7

## OPA2834IDGKR
designator U?
part A pins: 1, 2, 3, 4, 8
part B pins: 5, 6, 7

## OSC-TCXO-3.2x2.5
designator X?
pins: 1 GND, 2 GND, 3 OUT, 4 VCC

## OSC_SITIME_SIT11100A
designator X?
pins: 1, 2, 3, 4

## OSCILLATOR_4_PINS
designator X?
pins: 1 EN, 2 GND, 3 OUT, 4 VDD

## OSCILLATOR_4_PINS_TRI-STATE
designator X?
pins: 1 TRI-STATE (in), 2 GND, 3 OUT (out), 4 VDD (power)

## P401-M4GN-040-10-R
designator JP?
pins: 1, 2, 3, 4, 5, 6, 7, 8, 9, 10

## Patch_antenna_reference
designator ANT?
pins: 1

## PB_0402
designator PB?  (no BOM)
pins: 1, 2

## PC28F128M29EWLA
designator U?
pins: A2 A3, A3 A7, A4 RY/~{BY}, A5 ~{WE}, A6 A9, A7 A13, B2 A4, B3 A17, B4 Vpp/~{WP}, B5 ~{RST}, B6 A8, B7 A12, B8 A22, C2 A2, C3 A6, C4 A18, C5 A21, C6 A10, C7 A14, C8 RFU, D2 A1, D3 A5, D4 A20, D5 A19, D6 A11, D7 A15, D8 VCCQ, E2 A0, E3 DQ0, E4 DQ2, E5 DQ5, E6 DQ7, E7 A16, E8 VSS, F1 VCCQ, F2 ~{CE}, F3 DQ8, F4 DQ10, F5 DQ12, F6 DQ14, F7 ~{BYTE}, G2 ~{OE}, G3 DQ9, G4 DQ11, G5 VCC, G6 DQ13, G7 DQ15/A-1, H2 VSS, H3 DQ1, H4 DQ3, H5 DQ4, H6 DQ6, H7 VSS

## PCA9617A
designator U?
pins: 1 VCCA, 2 SCLA, 3 SDAA, 4 GND, 5 EN, 6 SDAB, 7 SCLB, 8 VCCB

## PCA9847
designator U?
pins: 1 VDD1, 2 A0, 3 ~{RESET}, 4 SD0, 5 SC0, 6 SD1, 7 SC1, 8 SD2, 9 SC2, 10 SD3, 11 SC3, 12 VSS, 13 SD4, 14 SC4, 15 SD5, 16 SC5, 17 SD6, 18 SC6, 19 SD7, 20 SC7, 21 A1, 22 SCL, 23 SDA, 24 VDD2

## PCB
designator HW?  (no BOM)

## PCB_ANT_ST60A2_DUAL-FEED_B2336
designator ANT?
pins: 1 F1 (hiz), 2 F2 (hiz), G1, G2, G3, G4, G5, G6, G7, G8, G9, G10, G11, G12, G13, G14, G15, G16, G17, G18, G19, G20, G21, G22, G23, G24, G25, G26

## PCB_mb1262
designator HW?  (mechanical)

## PCB_MB1265
designator HW?

## PCB_mb1299
designator HW?  (mechanical)

## PCB_MB1801
designator HW?

## PCB_MB1803
designator HW?

## PCB_MB1863
designator HW?

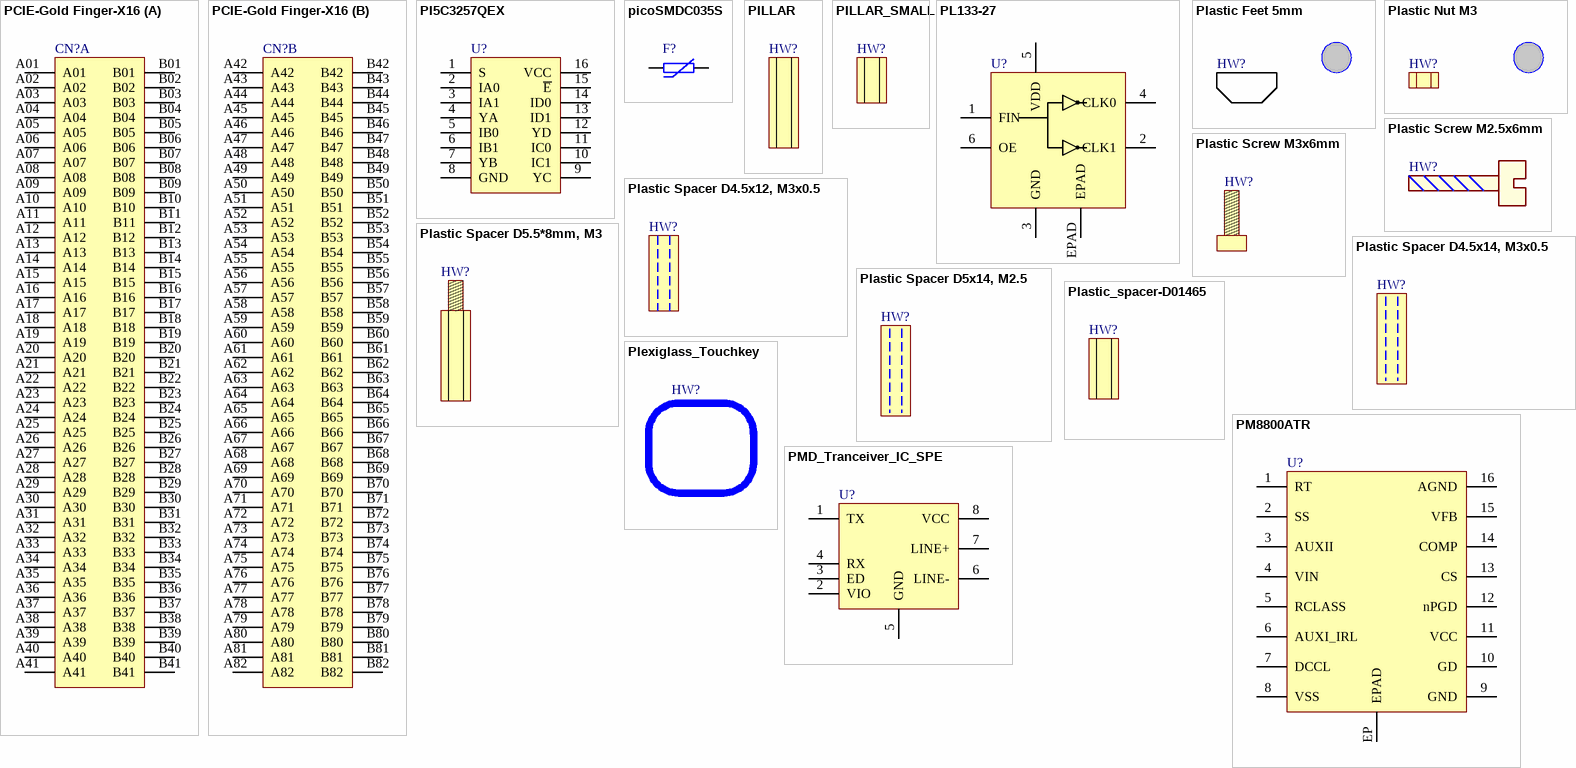
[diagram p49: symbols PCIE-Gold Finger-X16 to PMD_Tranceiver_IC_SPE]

## PCIE-Gold Finger-X16
designator CN?  (no BOM)
part A pins: A01, A02, A03, A04, A05, A06, A07, A08, A09, A10, A11, A12, A13, A14, A15, A16, A17, A18, A19, A20, A21, A22, A23, A24, A25, A26, A27, A28, A29, A30, A31, A32, A33, A34, A35, A36, A37, A38, A39, A40, A41, B01, B02, B03, B04, B05, B06, B07, B08, B09, B10, B11, B12, B13, B14, B15, B16, B17, B18, B19, B20, B21, B22, B23, B24, B25, B26, B27, B28, B29, B30, B31, B32, B33, B34, B35, B36, B37, B38, B39, B40, B41
part B pins: A42, A43, A44, A45, A46, A47, A48, A49, A50, A51, A52, A53, A54, A55, A56, A57, A58, A59, A60, A61, A62, A63, A64, A65, A66, A67, A68, A69, A70, A71, A72, A73, A74, A75, A76, A77, A78, A79, A80, A81, A82, B42, B43, B44, B45, B46, B47, B48, B49, B50, B51, B52, B53, B54, B55, B56, B57, B58, B59, B60, B61, B62, B63, B64, B65, B66, B67, B68, B69, B70, B71, B72, B73, B74, B75, B76, B77, B78, B79, B80, B81, B82

## PI5C3257QEX
designator U?
pins: 1 S, 2 IA0, 3 IA1, 4 YA, 5 IB0, 6 IB1, 7 YB, 8 GND, 9 YC, 10 IC1, 11 IC0, 12 YD, 13 ID1, 14 ID0, 15 ~{E}, 16 VCC

## picoSMDC035S
designator F?
pins: 1, 2

## PILLAR
designator HW?  (mechanical)

## PILLAR_SMALL
designator HW?  (mechanical)

## PL133-27
designator U?
pins: 1 FIN, 2 CLK1, 3 GND, 4 CLK0, 5 VDD, 6 OE, EPAD

## Plastic Feet 5mm
designator HW?  (mechanical)

## Plastic Nut M3
designator HW?  (mechanical)

## Plastic Screw M2.5x6mm
designator HW?  (mechanical)

## Plastic Screw M3x6mm
designator HW?  (mechanical)

## Plastic Spacer D4.5x12, M3x0.5
designator HW?  (mechanical)

## Plastic Spacer D4.5x14, M3x0.5
designator HW?  (mechanical)

## Plastic Spacer D5.5*8mm, M3
designator HW?  (mechanical)

## Plastic Spacer D5x14, M2.5
designator HW?  (mechanical)

## Plastic_spacer-D01465
designator HW?

## Plexiglass_Touchkey
designator HW?

## PM8800ATR
designator U?
pins: 1 RT, 2 SS, 3 AUXII, 4 VIN, 5 RCLASS, 6 AUXI_IRL, 7 DCCL, 8 VSS, 9 GND, 10 GD, 11 VCC, 12 nPGD, 13 CS, 14 COMP, 15 VFB, 16 AGND, EP EPAD

## PMD_Tranceiver_IC_SPE
designator U?
pins: 1 TX, 2 VIO, 3 ED, 4 RX, 5 GND, 6 LINE-, 7 LINE+, 8 VCC
1 alternate drawing of the same symbol

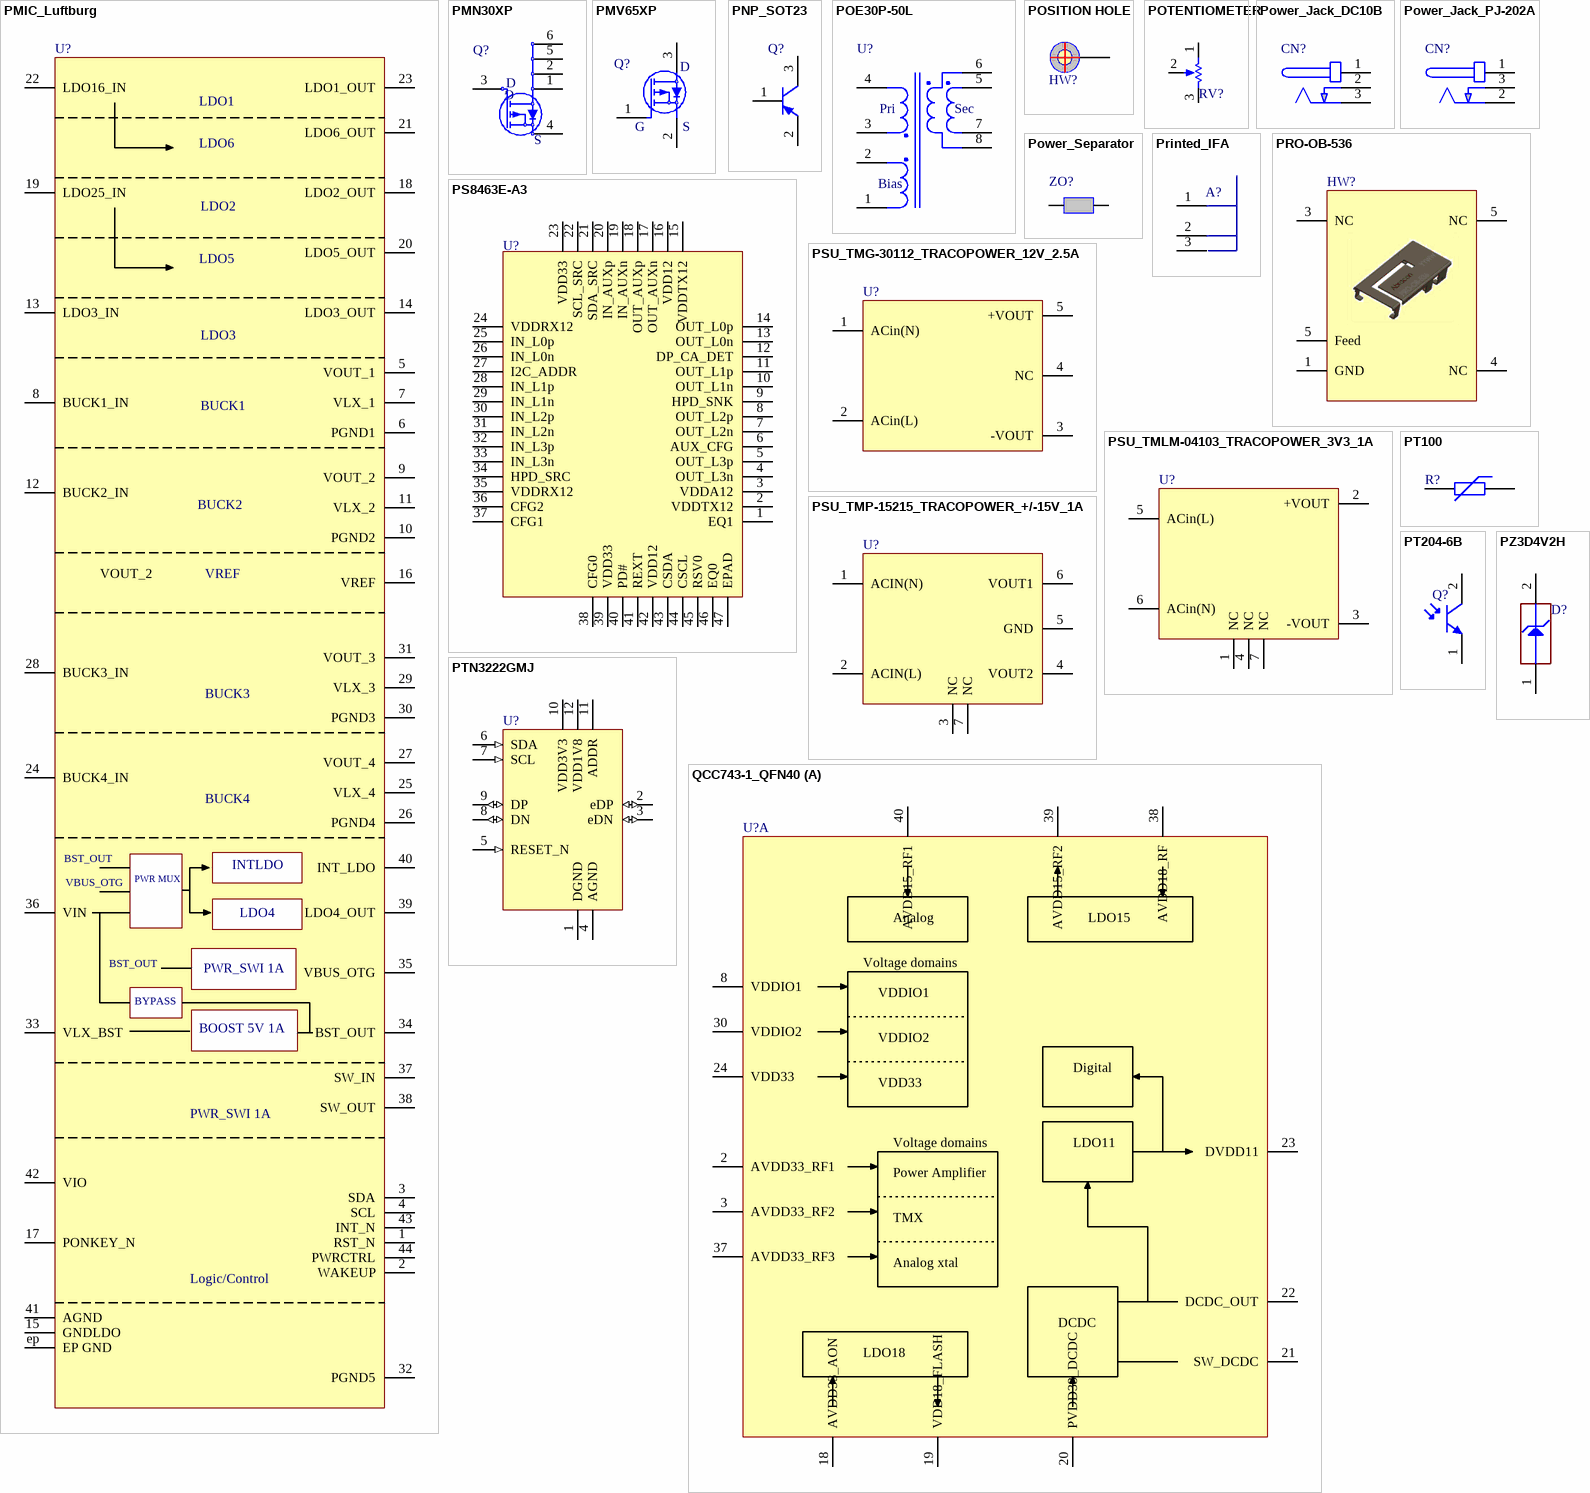
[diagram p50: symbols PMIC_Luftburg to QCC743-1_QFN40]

## PMIC_Luftburg
designator U?
pins: 1 RST_N, 2 WAKEUP, 3 SDA, 4 SCL, 5 VOUT_1, 6 PGND1, 7 VLX_1, 8 BUCK1_IN, 9 VOUT_2, 10 PGND2, 11 VLX_2, 12 BUCK2_IN, 13 LDO3_IN, 14 LDO3_OUT, 15 GNDLDO, 16 VREF, 17 PONKEY_N, 18 LDO2_OUT, 19 LDO25_IN, 20 LDO5_OUT, 21 LDO6_OUT, 22 LDO16_IN, 23 LDO1_OUT, 24 BUCK4_IN, 25 VLX_4, 26 PGND4, 27 VOUT_4, 28 BUCK3_IN, 29 VLX_3, 30 PGND3, 31 VOUT_3, 32 PGND5, 33 VLX_BST, 34 BST_OUT, 35 VBUS_OTG, 36 VIN, 37 SW_IN, 38 SW_OUT, 39 LDO4_OUT, 40 INT_LDO, 41 AGND, 42 VIO, 43 INT_N, 44 PWRCTRL, ep EP GND

## PMN30XP
designator Q?
pins: 1 S, 2 S, 3 G, 4 S, 5 D, 6 D

## PMV65XP
designator Q?
pins: 1 G, 2 S, 3 D

## PNP_SOT23
designator Q?
pins: 1 B, 2 E, 3 C

## POE30P-50L
designator U?
pins: 1, 2, 3, 4, 5, 6, 7, 8

## POSITION HOLE
designator HW?  (no BOM)
pins: 1

## POTENTIOMETER
designator RV?
pins: 1 BOT, 2 TAP, 3 TOP

## Power_Jack_DC10B
designator CN?
pins: 1, 2, 3

## Power_Jack_PJ-202A
designator CN?
pins: 1, 2, 3

## Power_Separator
designator ZO?  (net tie, no BOM)
pins: 1, 2

## Printed_IFA
designator A?
pins: 1, 2, 3

## PRO-OB-536
designator HW?
pins: 1 GND, 3 NC, 4 NC, 5 NC, 5 Feed

## PS8463E-A3
designator U?
pins: 1 EQ1, 2 VDDTX12, 3 VDDA12, 4 OUT_L3n, 5 OUT_L3p, 6 AUX_CFG, 7 OUT_L2n, 8 OUT_L2p, 9 HPD_SNK, 10 OUT_L1n, 11 OUT_L1p, 12 DP_CA_DET, 13 OUT_L0n, 14 OUT_L0p, 15 VDDTX12, 16 VDD12, 17 OUT_AUXn, 18 OUT_AUXp, 19 IN_AUXn, 20 IN_AUXp, 21 SDA_SRC, 22 SCL_SRC, 23 VDD33, 24 VDDRX12, 25 IN_L0p, 26 IN_L0n, 27 I2C_ADDR, 28 IN_L1p, 29 IN_L1n, 30 IN_L2p, 31 IN_L2n, 32 IN_L3p, 33 IN_L3n, 34 HPD_SRC, 35 VDDRX12, 36 CFG2, 37 CFG1, 38 CFG0, 39 VDD33, 40 PD#, 41 REXT, 42 VDD12, 43 CSDA, 44 CSCL, 45 RSV0, 46 EQ0, 47 EPAD

## PSU_TMG-30112_TRACOPOWER_12V_2.5A
designator U?
pins: 1 ACin(N) (power), 2 ACin(L) (power), 3 -VOUT (power), 4 NC (power), 5 +VOUT (power)

## PSU_TMLM-04103_TRACOPOWER_3V3_1A
designator U?
pins: 1 NC (power), 2 +VOUT (power), 3 -VOUT (power), 4 NC (power), 5 ACin(L) (power), 6 ACin(N) (power), 7 NC (power)

## PSU_TMP-15215_TRACOPOWER_+/-15V_1A
designator U?
pins: 1 ACIN(N) (power), 2 ACIN(L) (power), 3 NC (power), 4 VOUT2 (power), 5 GND (power), 6 VOUT1 (power), 7 NC (power)

## PT100
designator R?
pins: 1, 2

## PT204-6B
designator Q?
pins: 1 E, 2 C

## PTN3222GMJ
designator U?
pins: 1 DGND, 2 eDP (io), 3 eDN (io), 4 AGND, 5 RESET_N (in), 6 SDA (in), 7 SCL (in), 8 DN (io), 9 DP (io), 10 VDD3V3 (power), 11 ADDR (power), 12 VDD1V8 (power)

## PZ3D4V2H
designator D?
pins: 1 A, 2 K

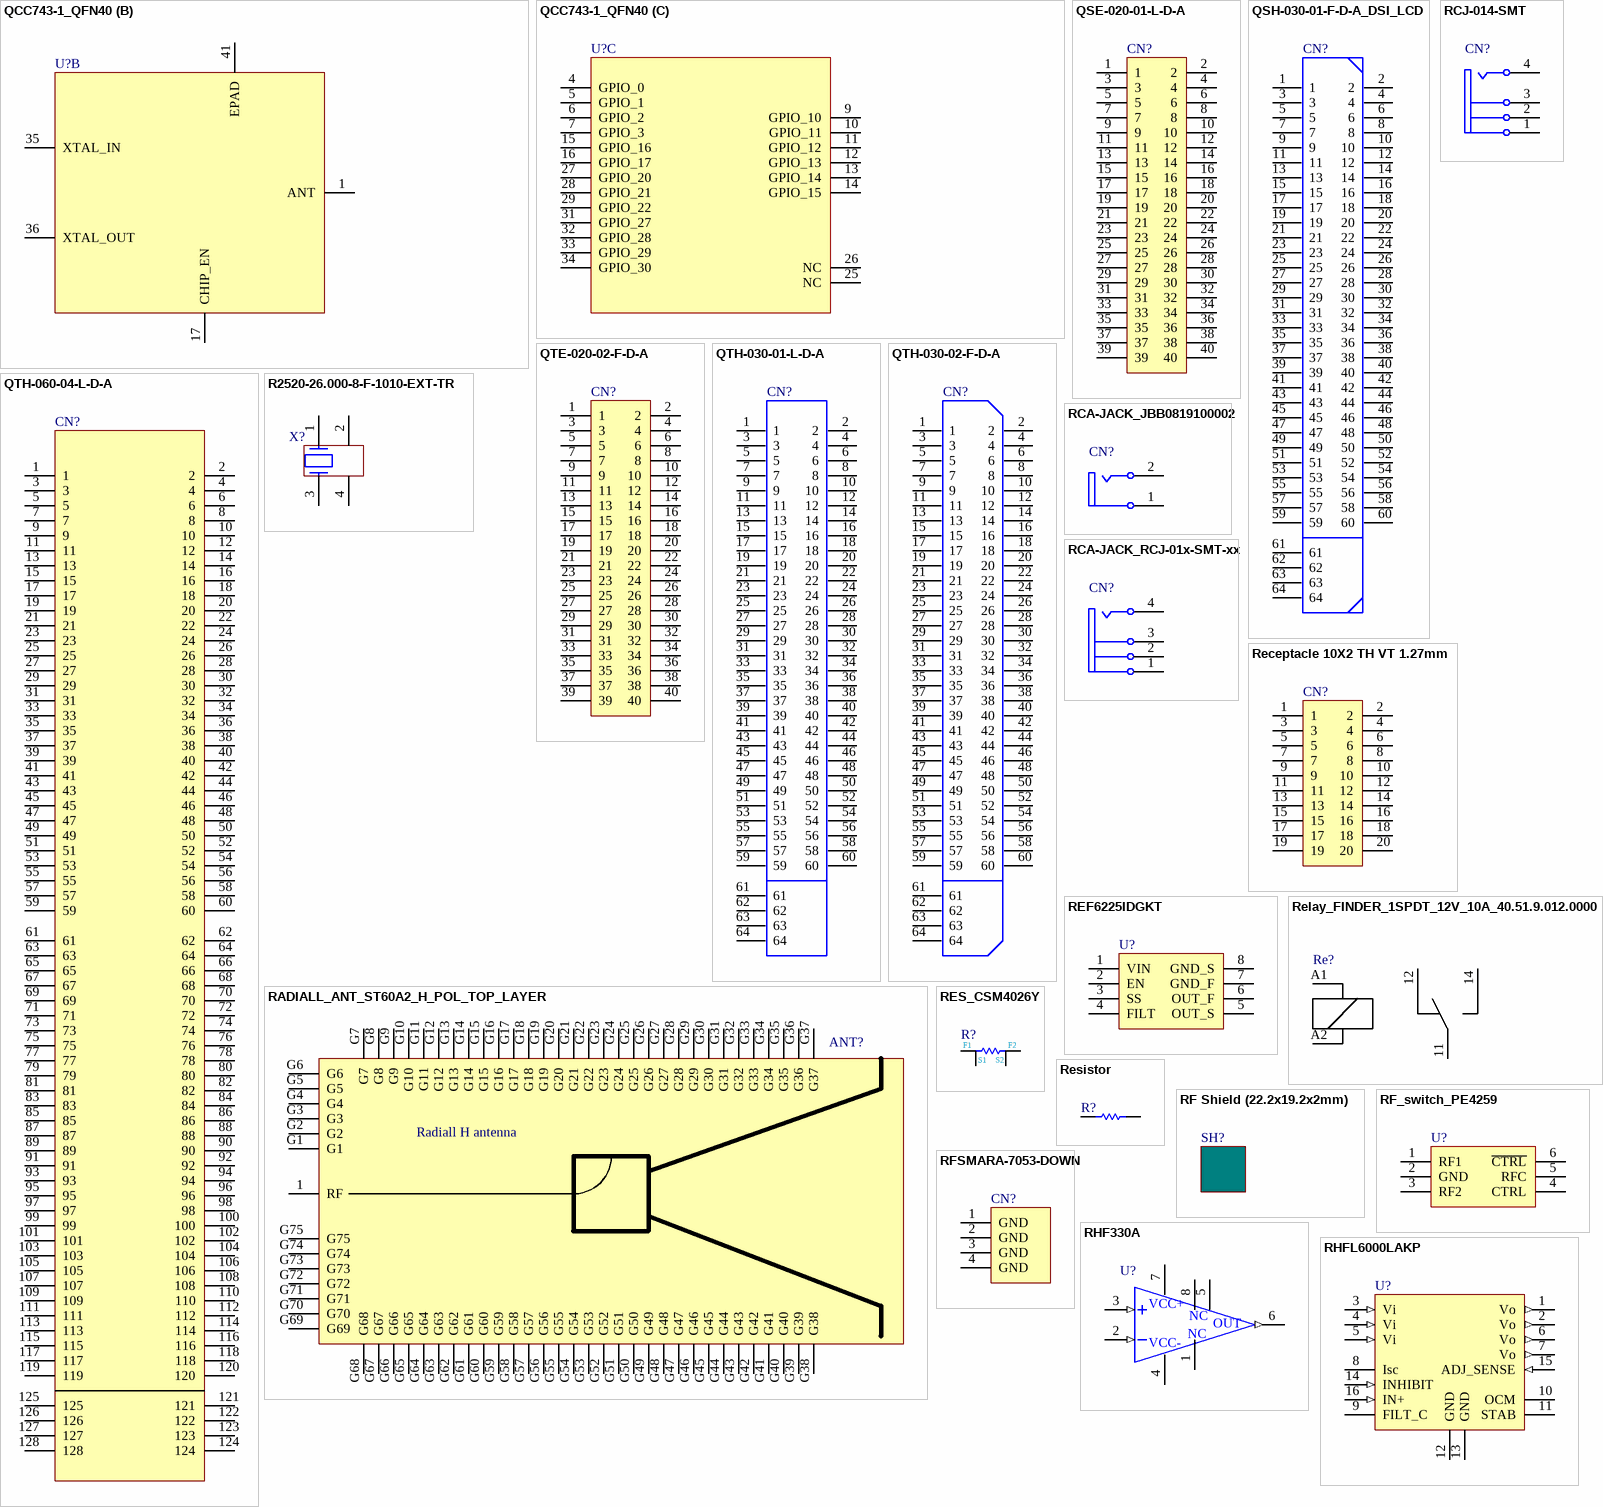
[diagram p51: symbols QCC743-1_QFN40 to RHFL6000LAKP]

## QCC743-1_QFN40
designator U?
part A pins: 2 AVDD33_RF1, 3 AVDD33_RF2, 8 VDDIO1, 18 AVDD33_AON, 19 VDD18_FLASH, 20 PVDD33_DCDC, 21 SW_DCDC, 22 DCDC_OUT, 23 DVDD11, 24 VDD33, 30 VDDIO2, 37 AVDD33_RF3, 38 AVDD18_RF, 39 AVDD15_RF2, 40 AVDD15_RF1
part B pins: 1 ANT, 17 CHIP_EN, 35 XTAL_IN, 36 XTAL_OUT, 41 EPAD
part C pins: 4 GPIO_0, 5 GPIO_1, 6 GPIO_2, 7 GPIO_3, 9 GPIO_10, 10 GPIO_11, 11 GPIO_12, 12 GPIO_13, 13 GPIO_14, 14 GPIO_15, 15 GPIO_16, 16 GPIO_17, 25 NC, 26 NC, 27 GPIO_20, 28 GPIO_21, 29 GPIO_22, 31 GPIO_27, 32 GPIO_28, 33 GPIO_29, 34 GPIO_30

## QSE-020-01-L-D-A
designator CN?
pins: 1, 2, 3, 4, 5, 6, 7, 8, 9, 10, 11, 12, 13, 14, 15, 16, 17, 18, 19, 20, 21, 22, 23, 24, 25, 26, 27, 28, 29, 30, 31, 32, 33, 34, 35, 36, 37, 38, 39, 40

## QSH-030-01-F-D-A_DSI_LCD
designator CN?
pins: 1, 2, 3, 4, 5, 6, 7, 8, 9, 10, 11, 12, 13, 14, 15, 16, 17, 18, 19, 20, 21, 22, 23, 24, 25, 26, 27, 28, 29, 30, 31, 32, 33, 34, 35, 36, 37, 38, 39, 40, 41, 42, 43, 44, 45, 46, 47, 48, 49, 50, 51, 52, 53, 54, 55, 56, 57, 58, 59, 60, 61, 62, 63, 64

## QTE-020-02-F-D-A
designator CN?
pins: 1, 2, 3, 4, 5, 6, 7, 8, 9, 10, 11, 12, 13, 14, 15, 16, 17, 18, 19, 20, 21, 22, 23, 24, 25, 26, 27, 28, 29, 30, 31, 32, 33, 34, 35, 36, 37, 38, 39, 40

## QTH-030-01-L-D-A
designator CN?
pins: 1, 2, 3, 4, 5, 6, 7, 8, 9, 10, 11, 12, 13, 14, 15, 16, 17, 18, 19, 20, 21, 22, 23, 24, 25, 26, 27, 28, 29, 30, 31, 32, 33, 34, 35, 36, 37, 38, 39, 40, 41, 42, 43, 44, 45, 46, 47, 48, 49, 50, 51, 52, 53, 54, 55, 56, 57, 58, 59, 60, 61, 62, 63, 64

## QTH-030-02-F-D-A
designator CN?
pins: 1, 2, 3, 4, 5, 6, 7, 8, 9, 10, 11, 12, 13, 14, 15, 16, 17, 18, 19, 20, 21, 22, 23, 24, 25, 26, 27, 28, 29, 30, 31, 32, 33, 34, 35, 36, 37, 38, 39, 40, 41, 42, 43, 44, 45, 46, 47, 48, 49, 50, 51, 52, 53, 54, 55, 56, 57, 58, 59, 60, 61, 62, 63, 64

## QTH-060-04-L-D-A
designator CN?
pins: 1, 2, 3, 4, 5, 6, 7, 8, 9, 10, 11, 12, 13, 14, 15, 16, 17, 18, 19, 20, 21, 22, 23, 24, 25, 26, 27, 28, 29, 30, 31, 32, 33, 34, 35, 36, 37, 38, 39, 40, 41, 42, 43, 44, 45, 46, 47, 48, 49, 50, 51, 52, 53, 54, 55, 56, 57, 58, 59, 60, 61, 62, 63, 64, 65, 66, 67, 68, 69, 70, 71, 72, 73, 74, 75, 76, 77, 78, 79, 80, 81, 82, 83, 84, 85, 86, 87, 88, 89, 90, 91, 92, 93, 94, 95, 96, 97, 98, 99, 100, 101, 102, 103, 104, 105, 106, 107, 108, 109, 110, 111, 112, 113, 114, 115, 116, 117, 118, 119, 120, 121, 122, 123, 124, 125, 126, 127, 128

## R2520-26.000-8-F-1010-EXT-TR
designator X?
pins: 1, 2, 3, 4

## RADIALL_ANT_ST60A2_H_POL_TOP_LAYER
designator ANT?
pins: 1 RF (hiz), G1, G2, G3, G4, G5, G6, G7, G8, G9, G10, G11, G12, G13, G14, G15, G16, G17, G18, G19, G20, G21, G22, G23, G24, G25, G26, G27, G28, G29, G30, G31, G32, G33, G34, G35, G36, G37, G38, G39, G40, G41, G42, G43, G44, G45, G46, G47, G48, G49, G50, G51, G52, G53, G54, G55, G56, G57, G58, G59, G60, G61, G62, G63, G64, G65, G66, G67, G68, G69, G70, G71, G72, G73, G74, G75

## RCA-JACK_JBB0819100002
designator CN?
pins: 1 Ground (power) "Outer Shield (Sleeve)", 2 Signal "Center Pin (Plug Tip)"

## RCA-JACK_RCJ-01x-SMT-xx
designator CN?
pins: 1 Ground (power) "Outer Shield (Sleeve)", 2 Ground (power) "Outer Shield (Sleeve)", 3 Ground (power) "Outer Shield (Sleeve)", 4 Signal "Center Pin (Plug Tip)"

## RCJ-014-SMT
designator CN?
pins: 1 Ground (power) "Outer Shield (Sleeve)", 2 Ground (power) "Outer Shield (Sleeve)", 3 Ground (power) "Outer Shield (Sleeve)", 4 Signal "Center Pin (Plug Tip)"

## Receptacle 10X2 TH VT 1.27mm
designator CN?
pins: 1, 2, 3, 4, 5, 6, 7, 8, 9, 10, 11, 12, 13, 14, 15, 16, 17, 18, 19, 20

## REF6225IDGKT
designator U?
pins: 1 VIN, 2 EN, 3 SS, 4 FILT, 5 OUT_S, 6 OUT_F, 7 GND_F, 8 GND_S

## Relay_FINDER_1SPDT_12V_10A_40.51.9.012.0000
designator Re?
pins: 11, 12, 14, A1, A2

## RES_CSM4026Y
designator R?
pins: F1 1, F2 2, S1 3, S2 4

## Resistor
designator R?
pins: 1, 2

## RF Shield (22.2x19.2x2mm)
designator SH?

## RF_switch_PE4259
designator U?
pins: 1 RF1, 2 GND, 3 RF2, 4 CTRL, 5 RFC, 6 ~{CTRL}

## RFSMARA-7053-DOWN
designator CN?
pins: 1 GND, 2 GND, 3 GND, 4 GND

## RHF330A
designator U?
pins: 1 NC, 2 IN- (in), 3 IN+ (in), 4 VCC-, 5 NC, 6 OUT (out), 7 VCC+, 8 NC

## RHFL6000LAKP
designator U?
pins: 1 Vo (out), 2 Vo (out), 3 Vi (in), 4 Vi (in), 5 Vi (in), 6 Vo (out), 7 Vo (out), 8 Isc, 9 FILT_C, 10 OCM (oc), 11 STAB, 12 GND, 13 GND, 14 INHIBIT (in), 15 ADJ_SENSE (in), 16 IN+ (in)

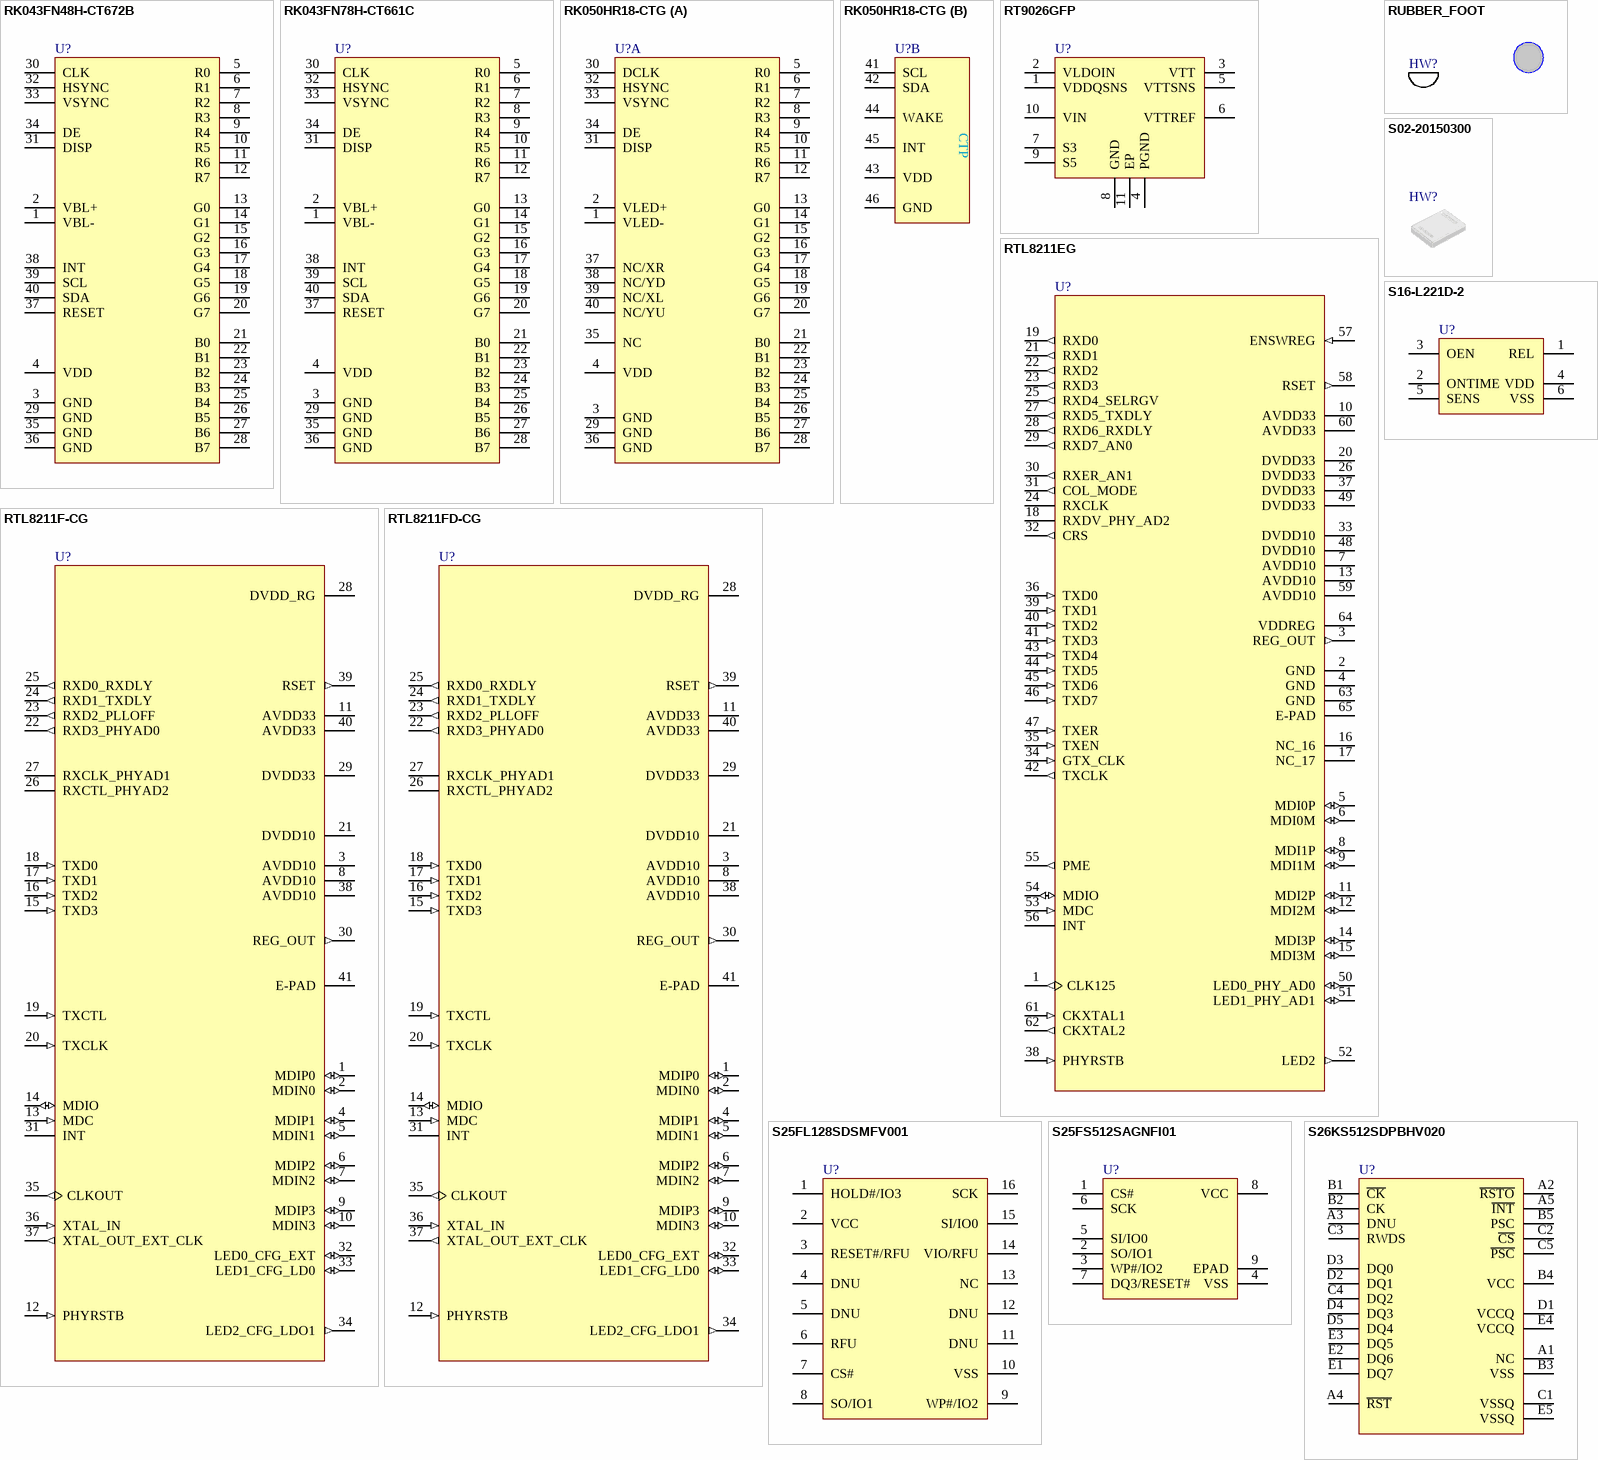
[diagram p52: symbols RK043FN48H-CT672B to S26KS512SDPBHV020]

## RK043FN48H-CT672B
designator U?
pins: 1 VBL-, 2 VBL+, 3 GND, 4 VDD, 5 R0, 6 R1, 7 R2, 8 R3, 9 R4, 10 R5, 11 R6, 12 R7, 13 G0, 14 G1, 15 G2, 16 G3, 17 G4, 18 G5, 19 G6, 20 G7, 21 B0, 22 B1, 23 B2, 24 B3, 25 B4, 26 B5, 27 B6, 28 B7, 29 GND, 30 CLK, 31 DISP, 32 HSYNC, 33 VSYNC, 34 DE, 35 GND, 36 GND, 37 RESET, 38 INT, 39 SCL, 40 SDA

## RK043FN78H-CT661C
designator U?
pins: 1 VBL-, 2 VBL+, 3 GND, 4 VDD, 5 R0, 6 R1, 7 R2, 8 R3, 9 R4, 10 R5, 11 R6, 12 R7, 13 G0, 14 G1, 15 G2, 16 G3, 17 G4, 18 G5, 19 G6, 20 G7, 21 B0, 22 B1, 23 B2, 24 B3, 25 B4, 26 B5, 27 B6, 28 B7, 29 GND, 30 CLK, 31 DISP, 32 HSYNC, 33 VSYNC, 34 DE, 35 GND, 36 GND, 37 RESET, 38 INT, 39 SCL, 40 SDA

## RK050HR18-CTG
designator U?
part A pins: 1 VLED-, 2 VLED+, 3 GND, 4 VDD, 5 R0, 6 R1, 7 R2, 8 R3, 9 R4, 10 R5, 11 R6, 12 R7, 13 G0, 14 G1, 15 G2, 16 G3, 17 G4, 18 G5, 19 G6, 20 G7, 21 B0, 22 B1, 23 B2, 24 B3, 25 B4, 26 B5, 27 B6, 28 B7, 29 GND, 30 DCLK, 31 DISP, 32 HSYNC, 33 VSYNC, 34 DE, 35 NC, 36 GND, 37 NC/XR, 38 NC/YD, 39 NC/XL, 40 NC/YU
part B pins: 41 SCL, 42 SDA, 43 VDD, 44 WAKE, 45 INT, 46 GND

## RT9026GFP
designator U?
pins: 1 VDDQSNS, 2 VLDOIN, 3 VTT, 4 PGND, 5 VTTSNS, 6 VTTREF, 7 S3, 8 GND, 9 S5, 10 VIN, 11 EP

## RTL8211EG
designator U?
pins: 1 CLK125 (out), 2 GND (power), 3 REG_OUT (out), 4 GND (power), 5 MDI0P (io), 6 MDI0M (io), 7 AVDD10 (power), 8 MDI1P (io), 9 MDI1M (io), 10 AVDD33 (power), 11 MDI2P (io), 12 MDI2M (io), 13 AVDD10 (power), 14 MDI3P (io), 15 MDI3M (io), 16 NC_16, 17 NC_17, 18 RXDV_PHY_AD2, 19 RXD0 (out), 20 DVDD33 (power), 21 RXD1 (out), 22 RXD2 (out), 23 RXD3 (out), 24 RXCLK, 25 RXD4_SELRGV (out), 26 DVDD33 (power), 27 RXD5_TXDLY (out), 28 RXD6_RXDLY (out), 29 RXD7_AN0 (out), 30 RXER_AN1 (out), 31 COL_MODE (out), 32 CRS (out), 33 DVDD10 (power), 34 GTX_CLK (in), 35 TXEN (in), 36 TXD0 (in), 37 DVDD33 (power), 38 PHYRSTB (in), 39 TXD1 (in), 40 TXD2 (in), 41 TXD3 (in), 42 TXCLK (out), 43 TXD4 (in), 44 TXD5 (in), 45 TXD6 (in), 46 TXD7 (in), 47 TXER (in), 48 DVDD10 (power), 49 DVDD33 (power), 50 LED0_PHY_AD0 (io), 51 LED1_PHY_AD1 (io), 52 LED2 (out), 53 MDC (in), 54 MDIO (io), 55 PME (out), 56 INT, 57 ENSWREG (in), 58 RSET (out), 59 AVDD10 (power), 60 AVDD33 (power), 61 CKXTAL1 (in), 62 CKXTAL2 (out), 63 GND (power), 64 VDDREG (power), 65 E-PAD (power)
